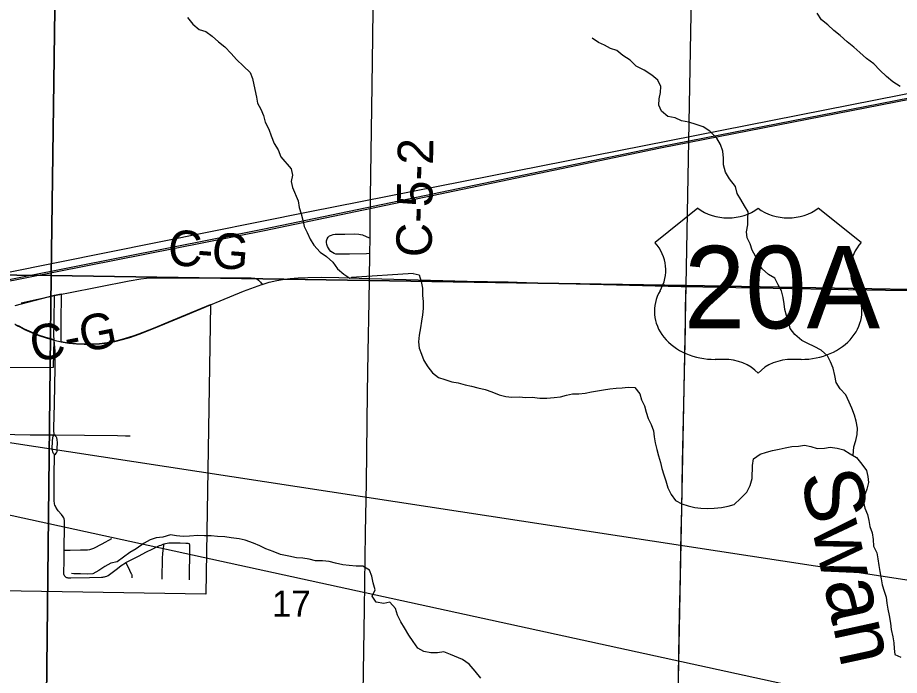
# Model space of a CAD drawing. Extents: x 0 to 42, y 0 to 22.
# Drawn here: x 7.178 to 8.588, y 16.836 to 17.887 of the extents above; entities that cross this region are included whole.
import ezdxf

# ---------------------------------------------------------------- set-up
doc = ezdxf.new("R2010")
doc.units = 0
for name, color, linetype in [('Default', 7, 'Continuous'), ('GM_X_City_Street', 7, 'Continuous'), ('GM_X_Corporation', 7, 'Continuous'), ('GM_X_County_Road', 7, 'Continuous'), ('GM_X_County_Road_Text', 7, 'Continuous'), ('GM_X_Minor_River', 7, 'Continuous'), ('GM_X_Minor_River_Text', 7, 'Continuous'), ('GM_X_Rail_Line', 7, 'Continuous'), ('GM_X_Section', 7, 'Continuous'), ('GM_X_Section_Text', 7, 'Continuous'), ('GM_X_State_Route', 7, 'Continuous'), ('GM_X_Township_Road', 7, 'Continuous'), ('GM_X_US_Location', 7, 'Continuous'), ('GM_X_US_Route', 7, 'Continuous'), ('GM_X_US_Shield', 7, 'Continuous'), ('SH_Text', 7, 'Continuous')]:
    doc.layers.add(name, color=color, linetype=linetype)

msp = doc.modelspace()

# ---------------------------------------------------------------- linework, layer by layer
at = {"layer": 'Default'}
for points in [[(8.9, 17.4474), (8.9, 18.4589), (8.2652, 18.4704), (8.2465, 17.4593)], [(8.9, 16.4352), (8.9, 17.4474), (8.2465, 17.4593), (8.2267, 16.4466)]]:
    msp.add_lwpolyline(points, close=True, dxfattribs=at)
at = {"layer": 'GM_X_City_Street'}
for points in [[(7.2365, 17.2209), (7.2361, 17.2286), (7.2361, 17.2314), (7.2368, 17.2702), (7.2379, 17.328), (7.2383, 17.3541), (7.2364, 17.3717), (7.2358, 17.3798), (7.2361, 17.3829), (7.2364, 17.3952), (7.2363, 17.4106), (7.2369, 17.4352), (7.237, 17.4431)], [(6.5131, 17.232), (6.5364, 17.2314), (6.5892, 17.2302), (6.6482, 17.2289), (6.7382, 17.2271), (6.9588, 17.2243), (7.1235, 17.2222), (7.1981, 17.2209), (7.226, 17.2209), (7.2365, 17.2209), (7.2384, 17.2208), (7.2851, 17.22), (7.3379, 17.2196), (7.3503, 17.2193), (7.3579, 17.2189)], [(7.2372, 17.1886), (7.2362, 17.19), (7.2356, 17.1908), (7.2348, 17.192), (7.2343, 17.1933), (7.2337, 17.1954), (7.2336, 17.1961), (7.2334, 17.1981), (7.2338, 17.2104), (7.234, 17.213), (7.2341, 17.2141), (7.2342, 17.2149), (7.2346, 17.2168), (7.2351, 17.2183), (7.2365, 17.2209)], [(7.2372, 17.1886), (7.2384, 17.1899), (7.2394, 17.1912), (7.24, 17.1921), (7.2408, 17.1935), (7.241, 17.1941), (7.2412, 17.1949), (7.2414, 17.1956), (7.2415, 17.1963), (7.2415, 17.1978), (7.2416, 17.209), (7.2414, 17.2122), (7.2411, 17.2136), (7.2409, 17.2146), (7.2405, 17.2157), (7.24, 17.2167), (7.2396, 17.2173), (7.2387, 17.2185), (7.2381, 17.2193), (7.2365, 17.2209)], [(7.255, 16.9935), (7.2538, 16.9945), (7.2531, 16.9952), (7.2528, 16.9958), (7.2524, 16.9967), (7.2521, 16.9979), (7.2521, 16.9991), (7.252, 17.0024), (7.2523, 17.0173), (7.2524, 17.033), (7.2524, 17.0364), (7.253, 17.0763), (7.2528, 17.084), (7.2525, 17.0865), (7.2519, 17.0882), (7.251, 17.0899), (7.2482, 17.0932), (7.2429, 17.0993), (7.2419, 17.1007), (7.2392, 17.1051), (7.2384, 17.1067), (7.2377, 17.1085), (7.2372, 17.1102), (7.2368, 17.112), (7.2365, 17.1139), (7.2364, 17.1155), (7.2362, 17.1183), (7.2362, 17.1388), (7.2365, 17.155), (7.2372, 17.1886)], [(7.2524, 17.0364), (7.2619, 17.0366), (7.2787, 17.0368), (7.2899, 17.0372), (7.2936, 17.0377), (7.2966, 17.0384), (7.3, 17.0398), (7.3133, 17.0466), (7.3286, 17.0549)], [(7.255, 16.9935), (7.2564, 16.9928), (7.2572, 16.9925), (7.2582, 16.9923), (7.2603, 16.9923), (7.2631, 16.9923), (7.2929, 16.9929), (7.3122, 16.9933), (7.3141, 16.9934), (7.3159, 16.9936), (7.3172, 16.9939), (7.3183, 16.9942), (7.3206, 16.9951), (7.3228, 16.9962), (7.327, 16.999), (7.3378, 17.0073), (7.3438, 17.0118), (7.3464, 17.0135), (7.348, 17.0145), (7.3491, 17.0152), (7.3512, 17.0165), (7.3533, 17.0177), (7.3721, 17.0273), (7.3832, 17.033), (7.3942, 17.0387), (7.405, 17.0436), (7.4074, 17.0446), (7.4107, 17.0459), (7.4124, 17.0464), (7.4143, 17.0469), (7.4171, 17.0475), (7.4198, 17.0479), (7.4248, 17.0483), (7.4304, 17.0482), (7.4379, 17.0479), (7.4472, 17.0476), (7.4487, 17.0475), (7.4502, 17.0474), (7.4511, 17.0472), (7.452, 17.0469), (7.4526, 17.0465)], [(7.4093, 16.9899), (7.4093, 16.9943), (7.4098, 17.0212), (7.4097, 17.0237), (7.41, 17.0311), (7.4105, 17.036), (7.4119, 17.0436), (7.4124, 17.0464)], [(7.4528, 16.9891), (7.4528, 17.0058), (7.4532, 17.0225), (7.4533, 17.0325), (7.4533, 17.0398), (7.4533, 17.0423), (7.4533, 17.0436), (7.4532, 17.0451), (7.453, 17.0458), (7.4526, 17.0465)], [(7.3613, 16.9922), (7.3613, 16.9934), (7.3612, 16.9946), (7.3611, 16.9956), (7.361, 16.9963), (7.3605, 16.9975), (7.3603, 16.9981), (7.3547, 17.0098), (7.3512, 17.0165)]]:
    msp.add_lwpolyline(points, dxfattribs=at)
at = {"layer": 'GM_X_Corporation'}
for points in [[(7.1741, 17.4273), (7.2368, 17.4436), (7.2479, 17.4458), (7.2476, 17.4353), (7.2471, 17.4107), (7.2471, 17.3953), (7.2469, 17.3699), (7.2596, 17.3678), (7.2719, 17.3665), (7.2843, 17.3659), (7.2966, 17.3659), (7.309, 17.3667), (7.3213, 17.3682), (7.3225, 17.3684), (7.3335, 17.3705), (7.345, 17.3733), (7.3625, 17.3786), (7.372, 17.3819), (7.3952, 17.3911), (7.4184, 17.4006), (7.4862, 17.4288), (7.4791, 16.966), (6.494, 16.9822)], [(6.7219, 17.3273), (7.2353, 17.3285), (7.2362, 17.3723), (7.2234, 17.3759), (7.2116, 17.3799), (7.2001, 17.3845), (7.1889, 17.3897), (7.1815, 17.3936), (7.1779, 17.3955)]]:
    msp.add_lwpolyline(points, dxfattribs=at)
at = {"layer": 'GM_X_County_Road'}
msp.add_line((7.1837, 17.4317), (7.237, 17.4431), dxfattribs=at)
for points in [[(7.7411, 17.5101), (7.7414, 17.535), (7.7418, 17.5645), (7.7428, 17.6359), (7.7449, 17.7788), (7.7459, 17.8564), (7.747, 17.9433), (7.7482, 18.0241), (7.7492, 18.1172), (7.7494, 18.1358), (7.7499, 18.1824), (7.7503, 18.229), (7.7513, 18.3035), (7.7538, 18.4779)], [(7.7406, 17.4706), (7.7407, 17.4807), (7.741, 17.4994), (7.7411, 17.5101)], [(7.237, 17.4431), (7.2481, 17.4453), (7.2593, 17.4475), (7.3566, 17.4669), (7.3748, 17.4701), (7.384, 17.4712), (7.3932, 17.4716), (7.4304, 17.4716), (7.4924, 17.4715), (7.5358, 17.4716), (7.5513, 17.4715), (7.5573, 17.4709), (7.5602, 17.4702), (7.563, 17.468), (7.5661, 17.4644), (7.569, 17.4609)], [(7.7246, 16.4117), (7.7245, 16.4183), (7.7242, 16.4307), (7.7257, 16.527), (7.7266, 16.5766), (7.7277, 16.6321), (7.7302, 16.775), (7.7324, 16.9428), (7.7342, 17.064), (7.7356, 17.1447), (7.7376, 17.2877), (7.7387, 17.3529), (7.74, 17.4337), (7.7406, 17.4706)], [(8.2323, 16.7021), (8.2335, 16.7724), (8.2363, 16.9341), (8.2371, 16.9745), (8.2376, 17.0024), (8.2384, 17.0366), (8.2389, 17.0646), (8.2397, 17.1019), (8.2411, 17.1765), (8.2431, 17.2697), (8.2446, 17.3444), (8.2456, 17.391), (8.246, 17.419), (8.2464, 17.4469), (8.2466, 17.4576)]]:
    msp.add_lwpolyline(points, dxfattribs=at)
at = {"layer": 'GM_X_Minor_River'}
for points in [[(8.5889, 17.7773), (8.5773, 17.7847), (8.5672, 17.7933), (8.5564, 17.803), (8.5468, 17.8134), (8.5352, 17.822), (8.5244, 17.8317), (8.5147, 17.8399), (8.5043, 17.8485), (8.4928, 17.8586), (8.4831, 17.8667), (8.4734, 17.8757), (8.4633, 17.8838), (8.4564, 17.8942)], [(7.4496, 17.8872), (7.4581, 17.8767), (7.4685, 17.8682), (7.4791, 17.8649), (7.4892, 17.8575), (7.4992, 17.8486), (7.5093, 17.8404), (7.5193, 17.83), (7.5282, 17.8203), (7.5393, 17.8094), (7.5497, 17.7997), (7.5533, 17.7898), (7.5558, 17.7799), (7.5599, 17.76), (7.5613, 17.7505), (7.5671, 17.7409), (7.5711, 17.7306), (7.5739, 17.7203), (7.5794, 17.7091), (7.5833, 17.6984), (7.5884, 17.6862), (7.5946, 17.6762), (7.5986, 17.6647), (7.6156, 17.6454), (7.6177, 17.6355), (7.6156, 17.6256), (7.6177, 17.6157), (7.6263, 17.5943), (7.6284, 17.5836), (7.6316, 17.5737), (7.634, 17.5638), (7.6361, 17.5535), (7.6408, 17.5439), (7.6456, 17.5331), (7.6518, 17.5235), (7.6618, 17.5127), (7.6719, 17.5053), (7.6819, 17.4963), (7.6893, 17.4859), (7.6994, 17.4774)], [(8.5136, 17.1876), (8.5148, 17.2013), (8.5181, 17.2115), (8.5205, 17.2213), (8.5207, 17.2315), (8.5187, 17.2426), (8.5162, 17.2521), (8.5115, 17.2632), (8.5072, 17.2728), (8.5021, 17.2843), (8.4928, 17.2944), (8.4869, 17.304), (8.4845, 17.3154), (8.4817, 17.3269), (8.4778, 17.3372), (8.473, 17.3468), (8.4626, 17.3561), (8.4517, 17.362), (8.4416, 17.3668), (8.4319, 17.3715), (8.4207, 17.3809), (8.4133, 17.3905), (8.4108, 17.4008), (8.4073, 17.4111), (8.4048, 17.4207), (8.4035, 17.4302), (8.4018, 17.4401), (8.3993, 17.4508), (8.3942, 17.4604), (8.3884, 17.4711), (8.3787, 17.477), (8.3686, 17.4856), (8.3612, 17.496), (8.3576, 17.5059), (8.3522, 17.5159), (8.3493, 17.5258), (8.3442, 17.5354), (8.3433, 17.5449), (8.3454, 17.5563), (8.3456, 17.5658), (8.3462, 17.5771), (8.3403, 17.5867), (8.3345, 17.5967), (8.3286, 17.6063), (8.3258, 17.6174), (8.3162, 17.6294), (8.3099, 17.6405), (8.3064, 17.652), (8.3066, 17.6626), (8.3053, 17.6736), (8.3017, 17.6843), (8.2959, 17.6947), (8.2847, 17.7056), (8.2743, 17.7126), (8.2626, 17.7163), (8.2513, 17.7199), (8.2392, 17.7224), (8.2291, 17.7272), (8.2178, 17.7293), (8.2073, 17.7375), (8.2034, 17.7471), (8.2039, 17.7577), (8.2057, 17.7675), (8.2066, 17.7774), (8.2015, 17.787), (8.1918, 17.7951), (8.1799, 17.8034), (8.1667, 17.8097), (8.1571, 17.819), (8.1455, 17.8265), (8.1358, 17.8346), (8.126, 17.8379), (8.1162, 17.843), (8.1065, 17.8474), (8.0964, 17.8544)], [(7.6994, 17.4774), (7.7091, 17.4707), (7.7118, 17.4718)], [(7.8104, 17.4782), (7.7118, 17.4718)], [(7.8104, 17.4782), (7.8202, 17.4761), (7.823, 17.4654), (7.8251, 17.4551), (7.8252, 17.4433), (7.8262, 17.4335), (7.8263, 17.4224), (7.8254, 17.4126), (7.8236, 17.402), (7.8219, 17.3918), (7.8198, 17.3797), (7.8192, 17.369), (7.8201, 17.3592), (7.8237, 17.3496), (7.8277, 17.3393), (7.8336, 17.3293), (7.8413, 17.3196), (7.851, 17.3122), (7.8608, 17.309), (7.8721, 17.3053), (7.8823, 17.3036), (7.8936, 17.3007), (7.9034, 17.2986), (7.914, 17.2958), (7.9253, 17.2933), (7.9362, 17.2896), (7.9478, 17.2848), (7.9584, 17.282), (7.9682, 17.281), (7.98, 17.2815), (7.9906, 17.2805), (8.0008, 17.2807), (8.0129, 17.279), (8.0243, 17.2791), (8.0356, 17.2804), (8.0459, 17.2813), (8.0554, 17.2838), (8.0649, 17.2859), (8.0755, 17.286), (8.0854, 17.2874), (8.0957, 17.2894), (8.1052, 17.2908), (8.1147, 17.2925), (8.1246, 17.2942), (8.1348, 17.2951), (8.1447, 17.2957), (8.1542, 17.2966), (8.1648, 17.2964), (8.1729, 17.2864), (8.1754, 17.2768), (8.1801, 17.2669), (8.1829, 17.2569), (8.1861, 17.247), (8.1909, 17.2374), (8.1945, 17.2271), (8.1958, 17.2176), (8.1975, 17.2077), (8.1999, 17.197), (8.2027, 17.187), (8.2056, 17.1764), (8.208, 17.1668), (8.2109, 17.1569), (8.2141, 17.147), (8.2173, 17.1359), (8.2231, 17.1255), (8.2297, 17.1159), (8.2399, 17.1104), (8.25, 17.1071), (8.2606, 17.1046), (8.2704, 17.1037), (8.281, 17.1031), (8.2916, 17.1033), (8.3034, 17.1045), (8.314, 17.1066), (8.3236, 17.1094), (8.3336, 17.1187), (8.344, 17.1292), (8.3492, 17.1397), (8.3524, 17.151), (8.3528, 17.1719), (8.3546, 17.1825), (8.365, 17.1899), (8.3752, 17.1931), (8.3848, 17.1955), (8.3954, 17.198), (8.4049, 17.1997), (8.4156, 17.2021), (8.4262, 17.2027), (8.4361, 17.204), (8.4459, 17.2019), (8.4561, 17.1987), (8.4678, 17.1992), (8.4773, 17.2009), (8.4883, 17.1991), (8.4988, 17.1967), (8.5089, 17.1904), (8.519, 17.1845), (8.5279, 17.174), (8.5349, 17.1637), (8.5374, 17.1541), (8.5383, 17.1446)], [(8.5383, 17.1446), (8.5358, 17.134), (8.5322, 17.1235), (8.5301, 17.1133), (8.5326, 17.1037), (8.5365, 17.0934), (8.539, 17.0838), (8.5403, 17.0743), (8.5443, 17.064), (8.5456, 17.0537), (8.5465, 17.0427), (8.5516, 17.0323), (8.5533, 17.0224), (8.555, 17.0121), (8.5567, 17.0022), (8.5584, 16.9904), (8.5601, 16.9809), (8.5633, 16.971), (8.5665, 16.9614), (8.5678, 16.9519), (8.5695, 16.9424), (8.5712, 16.9321), (8.5736, 16.9199), (8.5745, 16.9096), (8.5773, 16.8982), (8.5787, 16.8886), (8.5796, 16.8791), (8.5802, 16.8696), (8.5903, 16.8656)], [(7.7635, 16.9514), (7.7511, 16.9532), (7.7448, 16.9631), (7.7495, 16.9729), (7.7464, 16.9844), (7.7443, 16.9947), (7.7407, 17.0042), (7.7298, 17.0109), (7.7192, 17.0107), (7.7079, 17.0117), (7.6981, 17.0131), (7.6864, 17.0156), (7.6762, 17.0184), (7.6656, 17.0194), (7.6543, 17.0196), (7.6441, 17.0218), (7.6342, 17.0235), (7.624, 17.0241), (7.6116, 17.0266), (7.5984, 17.0295), (7.5867, 17.0343), (7.5751, 17.0383), (7.5653, 17.0435), (7.5552, 17.0475), (7.542, 17.0523), (7.5322, 17.0544), (7.5193, 17.0562), (7.5091, 17.0575), (7.4974, 17.0581), (7.4872, 17.0591), (7.477, 17.0593), (7.466, 17.0599), (7.4527, 17.059), (7.4425, 17.0585), (7.4323, 17.0594), (7.4225, 17.0611), (7.4103, 17.0572), (7.3996, 17.0559), (7.3897, 17.0527), (7.3801, 17.0476), (7.3675, 17.0383), (7.3575, 17.0325), (7.3475, 17.0251), (7.3371, 17.0177), (7.3272, 17.0156), (7.3176, 17.0101), (7.308, 17.0038), (7.2985, 16.9987), (7.289, 16.9981), (7.2788, 16.9984), (7.2678, 16.9986), (7.264, 16.999)], [(7.9187, 16.8321), (7.9095, 16.8429), (7.9002, 16.8541), (7.8894, 16.8619), (7.8699, 16.8699), (7.8593, 16.8739), (7.8495, 16.8722), (7.8389, 16.8724), (7.8275, 16.8745), (7.8178, 16.88), (7.8104, 16.8905), (7.8034, 16.9008), (7.7965, 16.9124), (7.7906, 16.922), (7.7855, 16.9327), (7.7819, 16.943), (7.773, 16.9531), (7.7635, 16.9514)]]:
    msp.add_lwpolyline(points, dxfattribs=at)
at = {"layer": 'GM_X_Rail_Line'}
for points in [[(4.4738, 16.9443), (5.2911, 17.1083), (5.3521, 17.1586), (5.3953, 17.2101), (5.4468, 17.276), (5.4779, 17.3324), (5.5342, 17.3923), (5.5893, 17.4474), (5.618, 17.4689), (5.6635, 17.4809), (6.1368, 17.4838), (6.5418, 17.4827), (6.748, 17.4796), (7.1583, 17.4796), (7.645, 17.5773), (8.6737, 17.7802), (8.9, 17.8248)], [(2.1, 16.459), (2.2129, 16.4808), (2.5454, 16.5465), (3.2154, 16.6797), (3.8608, 16.8081), (4.4734, 16.9293), (4.9678, 17.0293), (5.6609, 17.1675), (6.33, 17.2984), (6.9548, 17.4275), (7.5722, 17.5495), (8.2054, 17.6814), (8.8625, 17.8098), (8.9, 17.8172)], [(2.1, 16.4567), (2.2123, 16.4784), (2.5452, 16.5433), (3.215, 16.6775), (3.8612, 16.8058), (4.4739, 16.927), (4.9682, 17.0271), (5.6614, 17.1653), (6.3305, 17.2961), (6.9553, 17.4252), (7.5727, 17.5472), (8.2058, 17.6791), (8.8629, 17.8076), (8.9, 17.8149)]]:
    msp.add_lwpolyline(points, dxfattribs=at)
at = {"layer": 'GM_X_Section'}
for points in [[(6.2631, 18.4885), (7.2453, 18.4817), (7.2316, 17.475), (6.2427, 17.4846)], [(7.2453, 18.4817), (8.2652, 18.4704), (8.2465, 17.4593), (7.2316, 17.475)], [(6.2427, 17.4846), (7.2316, 17.475), (7.2205, 16.4649), (6.2249, 16.4863), (6.224, 16.494)], [(7.2316, 17.475), (8.2465, 17.4593), (8.2267, 16.4466), (7.2205, 16.4649)]]:
    msp.add_lwpolyline(points, close=True, dxfattribs=at)
at = {"layer": 'GM_X_State_Route'}
msp.add_line((7.2364, 17.3717), (7.2476, 17.3693), dxfattribs=at)
for points in [[(7.569, 17.4609), (7.5803, 17.4643), (7.5924, 17.4671), (7.6017, 17.4688), (7.614, 17.4704), (7.6265, 17.4714), (7.642, 17.4721), (7.6638, 17.4724), (7.6918, 17.472), (7.7406, 17.4706)], [(7.7406, 17.4706), (7.897, 17.4663), (7.9623, 17.4649), (8.0058, 17.4637), (8.1146, 17.4609), (8.2389, 17.4577), (8.2466, 17.4576)], [(7.4864, 17.4282), (7.5017, 17.4346), (7.5391, 17.45), (7.5565, 17.4567), (7.5683, 17.4607), (7.569, 17.4609)], [(8.2466, 17.4576), (8.326, 17.456), (8.5654, 17.452), (8.612, 17.4513), (8.6991, 17.4497), (8.7644, 17.4488), (8.8483, 17.4476), (8.9, 17.4471)], [(7.2476, 17.3693), (7.2598, 17.3673), (7.2721, 17.366), (7.2845, 17.3653), (7.2969, 17.3654), (7.3092, 17.3661), (7.3215, 17.3677), (7.3227, 17.3679), (7.3337, 17.3699), (7.3457, 17.3728), (7.3576, 17.3763), (7.3723, 17.3814), (7.3954, 17.3905), (7.4472, 17.4118), (7.4864, 17.4282)], [(7.1734, 17.3977), (7.1742, 17.3972), (7.1781, 17.3949), (7.1817, 17.393), (7.1891, 17.3891), (7.2003, 17.3839), (7.2119, 17.3794), (7.2236, 17.3754), (7.2364, 17.3717)]]:
    msp.add_lwpolyline(points, dxfattribs=at)
at = {"layer": 'GM_X_Township_Road'}
for points in [[(7.7411, 17.5101), (7.7356, 17.51), (7.7085, 17.5095), (7.6869, 17.5093), (7.684, 17.5102), (7.6813, 17.5117), (7.679, 17.5138), (7.6768, 17.5162), (7.675, 17.5189), (7.6736, 17.5217), (7.6724, 17.5246), (7.6719, 17.5277), (7.6719, 17.5308), (7.6727, 17.5339), (7.6744, 17.5365), (7.6768, 17.5385), (7.6796, 17.5398), (7.6826, 17.5406), (7.6857, 17.541), (7.7014, 17.5414), (7.7171, 17.5416), (7.7233, 17.5413), (7.7264, 17.5408), (7.7294, 17.54), (7.7352, 17.5376), (7.7414, 17.535)], [(7.7246, 16.4117), (7.7245, 16.4183), (7.7242, 16.4307), (7.7257, 16.527), (7.7266, 16.5766), (7.7277, 16.6321), (7.7302, 16.775), (7.7324, 16.9428), (7.7342, 17.064), (7.7356, 17.1447), (7.7376, 17.2877), (7.7387, 17.3529), (7.74, 17.4337), (7.7406, 17.4706)]]:
    msp.add_lwpolyline(points, dxfattribs=at)
at = {"layer": 'GM_X_US_Route'}
msp.add_line((7.2364, 17.3717), (7.2476, 17.3693), dxfattribs=at)
for points in [[(7.569, 17.4609), (7.5803, 17.4643), (7.5924, 17.4671), (7.6017, 17.4688), (7.614, 17.4704), (7.6265, 17.4714), (7.642, 17.4721), (7.6638, 17.4724), (7.6918, 17.472), (7.7406, 17.4706)], [(7.7406, 17.4706), (7.897, 17.4663), (7.9623, 17.4649), (8.0058, 17.4637), (8.1146, 17.4609), (8.2389, 17.4577), (8.2466, 17.4576)], [(7.4864, 17.4282), (7.5017, 17.4346), (7.5391, 17.45), (7.5565, 17.4567), (7.5683, 17.4607), (7.569, 17.4609)], [(8.2466, 17.4576), (8.326, 17.456), (8.5654, 17.452), (8.612, 17.4513), (8.6991, 17.4497), (8.7644, 17.4488), (8.8483, 17.4476), (8.9, 17.4471)], [(7.2476, 17.3693), (7.2598, 17.3673), (7.2721, 17.366), (7.2845, 17.3653), (7.2969, 17.3654), (7.3092, 17.3661), (7.3215, 17.3677), (7.3227, 17.3679), (7.3337, 17.3699), (7.3457, 17.3728), (7.3576, 17.3763), (7.3723, 17.3814), (7.3954, 17.3905), (7.4472, 17.4118), (7.4864, 17.4282)], [(7.1734, 17.3977), (7.1742, 17.3972), (7.1781, 17.3949), (7.1817, 17.393), (7.1891, 17.3891), (7.2003, 17.3839), (7.2119, 17.3794), (7.2236, 17.3754), (7.2364, 17.3717)]]:
    msp.add_lwpolyline(points, dxfattribs=at)
at = {"layer": 'GM_X_US_Shield'}
for p, q in [((8.2657, 17.5829), (8.1971, 17.528)), ((8.5266, 17.528), (8.458, 17.5829)), ((8.2932, 17.3413), (8.3069, 17.3413)), ((8.4168, 17.3413), (8.4305, 17.3413))]:
    msp.add_line(p, q, dxfattribs=at)
for centre, major_axis, start_param, end_param in [((8.3138, 17.6222), (-0.0687, 0), 0.795399, 2.346194), ((8.4099, 17.6222), (-0.0687, 0), 0.795399, 2.346194), ((8.1183, 17.4839), (0.0961, 0), 5.838949, 6.894067), ((8.6054, 17.4839), (-0.0961, 0), 5.672304, 6.727422), ((8.2921, 17.4181), (0.0961, 0), 2.702327, 4.723529), ((8.4316, 17.4181), (-0.0961, 0), 1.559657, 3.580859), ((8.3069, 17.2863), (-0.0687, 0), 3.785094, 4.712389), ((8.4168, 17.2863), (-0.0687, 0), 4.712389, 5.639684)]:
    msp.add_ellipse(centre, major_axis=major_axis, ratio=0.8, start_param=start_param, end_param=end_param, dxfattribs=at)
at = {"layer": 'SH_Text'}
msp.add_lwpolyline([(9.439, 16.8599), (5.3926, 17.4787), (9.439, 16.5971)], close=True, dxfattribs=at)

# ---------------------------------------------------------------- texts
at = {"layer": 'GM_X_County_Road_Text'}
for s, height, rotation, p in [('C-5-2', 0.05682, 89.1292, (7.8399, 17.5041)), ('C', 0.0568, 358.6101, (7.4181, 17.4908)), ('G', 0.0568, 355.6103, (7.4867, 17.488)), ('-', 0.0568, 355.6945, (7.4637, 17.4897)), ('C-G', 0.05682, 11.4643, (7.2039, 17.3361))]:
    msp.add_text(s, height=height, rotation=rotation, dxfattribs=at).set_placement(p)
at = {"layer": 'GM_X_Minor_River_Text'}
msp.add_text('Swan', height=0.09476, rotation=282.2258, dxfattribs=at).set_placement((8.4292, 17.1561))
at = {"layer": 'GM_X_Section_Text'}
msp.add_text('17', height=0.04186, rotation=0, dxfattribs=at).set_placement((7.5845, 16.9301))
at = {"layer": 'GM_X_US_Location'}
for s in ['0', '/']:
    msp.add_text(s, height=0.000189, dxfattribs=at).set_placement((8.362, 17.4565))
msp.add_text('20A', height=0.000189, rotation=0, dxfattribs=at).set_placement((8.2979, 17.4173))
at = {"layer": 'GM_X_US_Shield'}
msp.add_text('20A', height=0.13184, dxfattribs=at).set_placement((8.2433, 17.3907))

doc.saveas('drawing.dxf')
